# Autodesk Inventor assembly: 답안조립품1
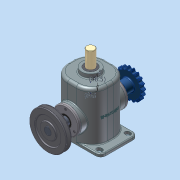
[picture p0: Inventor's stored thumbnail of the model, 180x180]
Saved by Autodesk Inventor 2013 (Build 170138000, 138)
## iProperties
Created: 2014-12
Part Number: 답안조립품1
Document SubType Name: Assembly
Designer: user
Author: user
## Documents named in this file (15)
- C:\Documents and Settings\user\바탕 화면\341208V1001\답안조립품1.iam
- C:\Documents and Settings\user\바탕 화면\341208V1001\본체.ipt
- C:\Documents and Settings\user\바탕 화면\341208V1001\편심축.ipt
- C:\Documents and Settings\user\바탕 화면\341208V1001\V-벨트풀리.ipt
- C:\Documents and Settings\user\바탕 화면\341208V1001\체인 스프로킷.ipt
- C:\Documents and Settings\user\바탕 화면\341208V1001\커버.ipt
- C:\Documents and Settings\user\바탕 화면\341208V1001\슬라이드.ipt
- C:\Documents and Settings\user\바탕 화면\341208V1001\가변스프링.ipt
- C:\Documents and Settings\user\바탕 화면\341208V1001\베어링 6205.ipt
- C:\Documents and Settings\user\바탕 화면\341208V1001\오일실.ipt
- C:\Documents and Settings\user\바탕 화면\341208V1001\부시.ipt
- C:\Documents and Settings\user\바탕 화면\341208V1001\키 8x8.ipt
- C:\Documents and Settings\user\바탕 화면\341208V1001\멈춤링.ipt
- C:\Documents and Settings\user\바탕 화면\341208V1001\M4x0.5.ipt
- C:\Documents and Settings\user\바탕 화면\341208V1001\멈춤나사 M5x0.5.ipt
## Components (9 placed, 4 different names)
1. V-벨트풀리:1
2. 5-체인 스프로킷:1
3. 가변스프링:1
4. M4x0.5:1
5. M4x0.5:2
6. M4x0.5:3
7. M4x0.5:4
8. M4x0.5:5
9. M4x0.5:6
